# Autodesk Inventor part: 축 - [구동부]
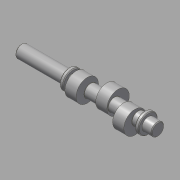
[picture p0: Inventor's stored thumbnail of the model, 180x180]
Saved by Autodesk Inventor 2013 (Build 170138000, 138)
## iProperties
Company: 한국ATC센터
Created: 2014-08
Part Number: 축 - [구동부]
Document SubType Name: Modeling
Designer: KYOUNG IL JANG
Density: 7.86 g/cm^3
Material: 강철, 연강
Mass: 516.584 g
Surface Area: 162.515 cm^2
Volume: 65.7231 cm^3
Author: KYOUNG IL JANG
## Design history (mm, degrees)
sketch "스케치1"
  geometry: L1 (-91.5, 0)-(91.5, 0); L2 (-91.5, 0)-(-91.5, 8.5); L3 (-91.5, 8.5)-(-27.5, 8.5); L4 (-27.5, 8.5)-(-27.5, 13); L5 (-27.5, 13)-(-22.5, 13); L6 (-22.5, 13)-(-22.5, 8.5); L7 (-22.5, 8.5)-(73.5, 8.5); L8 (73.5, 8.5)-(73.5, 13); L9 (73.5, 13)-(78.5, 13); L10 (78.5, 13)-(78.5, 8.5); L11 (78.5, 8.5)-(91.5, 8.5); L12 (91.5, 8.5)-(91.5, 0); 2 further points
  constraints: 24 end point, 5 parallel, 1 coincident, 1 horizontal, 1 midpoint, 1 perpendicular
  dimensions: "d0" = 183 distance of L1.start L1.end (derived); "d2" = 17 diameter of L3 L1; "d3" = 26 diameter of L5 L1; "d4" = 17 diameter of L7 L1; "d5" = 26 diameter of L9 L1; "d6" = 17 diameter of L11 L1; "d7" = 5 distance of L8.end L9.end; "d8" = 5 distance of L4.end L5.end; "d10" = 64 distance of L2.end L3.end; "d11" = 13 distance of L10.end L11.end; "d35" = 96 distance between parallel lines of L8 L6
revolve "회전1" sketch "스케치1" stored, may be unused: angle "d12" = 90 deg
node "작업 평면7"
sketch "스케치6"
  geometry: C1 r 15 at (0, 5); 1 further point
  constraints: 1 centre point, 1 vertical alignment
  dimensions: "d37" = 30 diameter of C1; "d38" = 5 distance of C1.centre point (0, 0)
extrude "돌출4" join sketch "스케치6" stored distance "d33" = 15; taper "d34" = 0 deg
node "작업 평면8"
sketch "스케치7"
  geometry: L1 (0, 0)-(-6.5, -11.258); L2 (0, 0)-(13, 0); C1 r 15 at (-2.5, -4.33); A1 r 13 centre (0, 0) between (-6.5, -11.258) and (13, 0) reference; 1 further point
  constraints: 4 end point, 2 point on circle, 1 centre point, 1 horizontal, 1 point on line
  dimensions: "d40" = 120 deg angle of L1 L2; "d41" = 30 diameter of C1; "d42" = 5 distance of point (0, 0) C1.centre
extrude "돌출5" join sketch "스케치7" stored distance "d43" = 15; taper "d44" = 0 deg
node "작업 평면9"
sketch "스케치8"
  geometry: L1 (0, 0)-(4.25, -7.361); L2 (0, 0)-(-8.5, 0); C1 r 15 at (2.5, -4.33); A1 r 8.5 centre (0, 0) between (4.25, -7.361) and (-8.5, 0) reference; 1 further point
  constraints: 4 end point, 2 point on circle, 1 centre point, 1 horizontal, 1 point on line
  dimensions: "d46" = 120 deg angle of L1 L2; "d47" = 30 diameter of C1; "d48" = 5 distance of point (0, 0) C1.centre
extrude "돌출6" join sketch "스케치8" stored distance "d49" = 15; taper "d50" = 0 deg
node "작업 평면3"
sketch "스케치5"
  geometry: L1 (32, 8.5)-(32, -8.5) reference; L2 (27.5, -2.5)-(14.5, -2.5); L3 (14.5, 2.5)-(27.5, 2.5); A1 r 2.5 centre (14.5, 0) between (14.5, 2.5) and (14.5, -2.5); A2 r 2.5 centre (27.5, 0) between (27.5, -2.5) and (27.5, 2.5); 4 further points
  constraints: 4 end point, 4 point on circle, 4 tangent, 2 centre point, 2 point on line, 1 horizontal alignment, 1 midpoint, 1 parallel, 1 perpendicular
  dimensions: "d23" = 5 distance between parallel lines of L3 L2; "d36" = 20 dimension on A1 L1; "d52" = 2 distance edge to line of A2 L1
extrude "돌출3" cut sketch "스케치5" distance "d25" = 3; taper "d26" = 0 deg
chamfer "모따기1" distance "d27" = 1; stored, may be unused: second distance "d28" = 2, angle "d29" = 45 deg
fillet "모깎기1" dims "d51" = 0.3
chamfer "모따기2" distance "d53" = 1; stored, may be unused: second distance "d54" = 2, angle "d55" = 45 deg
node "작업 평면10"
node "솔리드1"
other parameters: "d39" = -32, "d45" = 32
